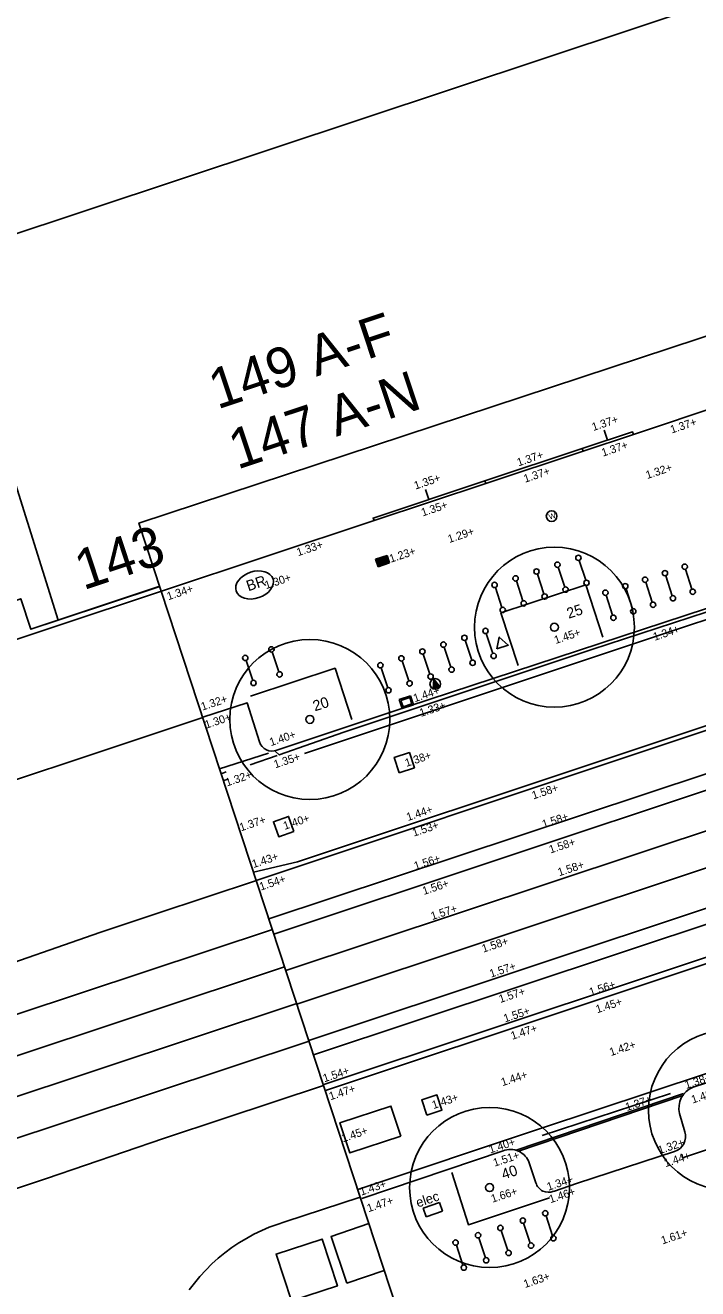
# Model space of a CAD drawing. Extents: x 122462 to 123306, y 485548 to 486417.
# Drawn here: x 122661.18 to 122686.41, y 486120.56 to 486167.94 of the extents above; entities that cross this region are included whole.
import ezdxf

# ---------------------------------------------------------------- set-up
doc = ezdxf.new("R2010")
doc.units = 0
for name, color, linetype in [('B meubilair trammast', 7, 'Continuous'), ('B RWS-band 115-225x250 mm specie', 7, 'Continuous'), ('B-WE-AL-WERKGRENS-G', 7, 'Continuous'), ('B-WE-GR-BOOM-S', 7, 'Continuous'), ('B-WE-GR-BOOM_BOOMDIAMETER', 7, 'Continuous'), ('B-WE-IE-MEUBILAIR_ELECTRAKAST', 7, 'Continuous'), ('B-WE-IE-MEUBILAIR_WEGMEUBILAIR-S', 7, 'Continuous'), ('B-WE-IE-MEUBILAIR_WEGMEUBILAIR_FIETSNIETJE-S', 7, 'Continuous'), ('B-WE-OG-BEBOUWING_PORTIEK1-G', 7, 'Continuous'), ('B-WE-OG-BEBOUWING_RAAM-G', 7, 'Continuous'), ('B-WE-OG-HOOGTEPUNT-S', 7, 'Continuous'), ('B-WE-OG-TOPOGRAFIE_RAILS-G', 7, 'Continuous'), ('B-WE-OG-TOPOKAART-G', 7, 'Continuous'), ('B-WE-RI-HWA_KOLK-S', 7, 'Continuous'), ('B-WE-RI-HWA_RIOOLPUT-S', 7, 'Continuous'), ('B-WE-VH-KANTOPSLUITING_OPSLUITBAND_100X200-G', 7, 'Continuous'), ('B-WE-VH-KANTOPSLUITING_TROTTOIRBAND_180 200-G', 7, 'Continuous'), ('B-WE-VH-KANTVERHARDING_EIND_VERHARDING-G', 7, 'Continuous'), ('B-WE-VH-MATERIAALGRENS_ASFALT-G', 7, 'Continuous'), ('B-WE-VW-MARKERING_LANGS_STREEP_11_010-G', 7, 'Continuous'), ('B-WE-VW-MARKERING_LANGS_STREEP_DOORGETROKKEN_010-G', 7, 'Continuous'), ('B-WE-VW-MARKERING_OVERIG-G', 7, 'Continuous'), ('Level 1', 7, 'Continuous'), ('Level 10', 7, 'Continuous'), ('Level 17', 7, 'Continuous'), ('Level 37', 7, 'Continuous'), ('Level 4', 7, 'Continuous'), ('Level 42', 7, 'Continuous'), ('Level 5', 7, 'Continuous'), ('Level 58', 7, 'Continuous')]:
    doc.layers.add(name, color=color, linetype=linetype)

msp = doc.modelspace()

# ---------------------------------------------------------------- linework, layer by layer
at = {"layer": 'B meubilair trammast'}
msp.add_lwpolyline([(122678.868, 486144.556), (122679.296, 486144.696), (122678.961, 486144.996)], close=True, dxfattribs=at)
at = {"layer": 'B RWS-band 115-225x250 mm specie'}
for points in [[(122669.847, 486135.87), (122698.323, 486145.37), (122705.772, 486147.833)], [(122708.301, 486140.155), (122702.829, 486138.34), (122672.345, 486128.207)]]:
    msp.add_lwpolyline(points, dxfattribs=at)
at = {"layer": 'B-WE-AL-WERKGRENS-G'}
msp.add_lwpolyline([(122857.632, 486078.279), (122830.484, 486160.606), (122900.937, 486183.81), (122887.855, 486222.555), (122665.445, 486149.273), (122678.196, 486110.449), (122807.072, 486152.895), (122835.324, 486068.154)], dxfattribs=at)
at = {"layer": 'B-WE-GR-BOOM-S'}
for centre, radius in [((122681.029, 486145.368), 3), ((122681.029, 486145.368), 0.15), ((122671.856, 486141.911), 3), ((122671.856, 486141.911), 0.15), ((122687.555, 486127.259), 3), ((122678.598, 486124.358), 3), ((122678.598, 486124.358), 0.15)]:
    msp.add_circle(centre, radius, dxfattribs=at)
for centre, start, end in [((122681.029, 486145.368), 0, 180), ((122681.029, 486145.368), 180, 0), ((122671.856, 486141.911), 0, 180), ((122671.856, 486141.911), 180, 0), ((122678.598, 486124.358), 0, 180), ((122678.598, 486124.358), 180, 0)]:
    msp.add_arc(centre, 0.15, start, end, dxfattribs=at)
at = {"layer": 'B-WE-IE-MEUBILAIR_ELECTRAKAST'}
for p, q in [((122676.103, 486123.588), (122676.718, 486123.797)), ((122676.215, 486123.257), (122676.103, 486123.588)), ((122676.83, 486123.466), (122676.215, 486123.257)), ((122676.718, 486123.797), (122676.83, 486123.466))]:
    msp.add_line(p, q, dxfattribs=at)
at = {"layer": 'B-WE-IE-MEUBILAIR_WEGMEUBILAIR-S'}
msp.add_lwpolyline([(122676.722, 486143.149), (122676.483, 486143.07), (122676.502, 486143.417), (122676.7, 486143.182), (122676.524, 486143.124), (122676.528, 486143.336), (122676.632, 486143.202), (122676.567, 486143.18), (122676.566, 486143.222), (122676.551, 486143.27)], dxfattribs=at)
for centre in [(122680.924, 486149.535), (122676.56, 486143.241)]:
    msp.add_circle(centre, 0.2, dxfattribs=at)
msp.add_ellipse((122669.784, 486146.953), major_axis=(-0.692, -0.23), ratio=0.685994, dxfattribs=at)
at = {"layer": 'B-WE-IE-MEUBILAIR_WEGMEUBILAIR_FIETSNIETJE-S'}
for p, q in [((122681.419, 486146.872), (122681.175, 486147.619)), ((122682.204, 486147.128), (122681.96, 486147.876)), ((122680.633, 486146.615), (122680.389, 486147.363)), ((122685.444, 486146.551), (122685.204, 486147.3)), ((122686.188, 486146.795), (122685.948, 486147.544)), ((122679.059, 486146.113), (122678.815, 486146.861)), ((122679.848, 486146.359), (122679.604, 486147.106)), ((122683.956, 486146.062), (122683.716, 486146.812)), ((122684.7, 486146.307), (122684.46, 486147.056)), ((122683.212, 486145.818), (122682.972, 486146.567)), ((122677.931, 486144.13), (122677.686, 486144.877)), ((122678.719, 486144.387), (122678.475, 486145.135)), ((122670.69, 486143.696), (122670.444, 486144.444)), ((122676.353, 486143.614), (122676.109, 486144.362)), ((122677.142, 486143.872), (122676.898, 486144.62)), ((122669.711, 486143.375), (122669.465, 486144.122)), ((122674.776, 486143.099), (122674.532, 486143.847)), ((122675.565, 486143.357), (122675.32, 486144.104)), ((122680.121, 486122.274), (122679.876, 486123.022)), ((122680.961, 486122.55), (122680.716, 486123.297)), ((122679.28, 486121.999), (122679.035, 486122.747)), ((122677.599, 486121.449), (122677.355, 486122.196)), ((122678.44, 486121.724), (122678.195, 486122.471))]:
    msp.add_line(p, q, dxfattribs=at)
for centre in [(122681.143, 486147.714), (122681.929, 486147.971), (122685.918, 486147.639), (122679.573, 486147.201), (122680.358, 486147.458), (122684.43, 486147.151), (122685.174, 486147.395), (122678.784, 486146.956), (122681.45, 486146.777), (122682.235, 486147.033), (122682.942, 486146.663), (122683.686, 486146.907), (122686.218, 486146.7), (122679.879, 486146.264), (122680.664, 486146.52), (122684.73, 486146.211), (122685.474, 486146.455), (122679.09, 486146.018), (122683.242, 486145.723), (122683.986, 486145.967), (122678.444, 486145.23), (122676.867, 486144.715), (122677.655, 486144.972), (122669.433, 486144.217), (122670.413, 486144.539), (122676.078, 486144.457), (122678.75, 486144.292), (122674.501, 486143.942), (122675.289, 486144.199), (122677.173, 486143.777), (122677.962, 486144.035), (122669.742, 486143.28), (122670.721, 486143.601), (122675.596, 486143.262), (122676.384, 486143.519), (122674.807, 486143.004), (122680.685, 486123.392), (122679.845, 486123.117), (122678.164, 486122.566), (122679.004, 486122.842), (122680.992, 486122.455), (122677.323, 486122.291), (122680.152, 486122.179), (122678.471, 486121.629), (122679.311, 486121.904), (122677.631, 486121.354)]:
    msp.add_circle(centre, 0.1, dxfattribs=at)
at = {"layer": 'B-WE-OG-BEBOUWING_PORTIEK1-G'}
for p, q in [((122683.019, 486152.379), (122682.893, 486152.757)), ((122676.325, 486150.16), (122676.2, 486150.536))]:
    msp.add_line(p, q, dxfattribs=at)
for points in [[(122682.106, 486151.971), (122683.995, 486152.598), (122683.963, 486152.693), (122682.074, 486152.066)], [(122674.262, 486149.366), (122678.452, 486150.758), (122678.42, 486150.856), (122674.229, 486149.464)]]:
    msp.add_lwpolyline(points, close=True, dxfattribs=at)
at = {"layer": 'B-WE-OG-BEBOUWING_RAAM-G'}
msp.add_lwpolyline([(122678.452, 486150.758), (122682.106, 486151.971), (122682.074, 486152.066), (122678.421, 486150.852)], close=True, dxfattribs=at)
at = {"layer": 'B-WE-OG-TOPOGRAFIE_RAILS-G'}
for p, q in [((122670.505, 486133.859), (122714.919, 486148.627)), ((122670.96, 486132.492), (122715.373, 486147.26)), ((122671.366, 486131.239), (122712.39, 486144.878)), ((122671.82, 486129.872), (122712.845, 486143.511))]:
    msp.add_line(p, q, dxfattribs=at)
at = {"layer": 'B-WE-OG-TOPOKAART-G'}
for points in [[(122683.995, 486152.598), (122687.4, 486153.729)], [(122666.285, 486146.717), (122674.262, 486149.366)]]:
    msp.add_lwpolyline(points, dxfattribs=at)
at = {"layer": 'B-WE-RI-HWA_KOLK-S'}
for p, q in [((122674.323, 486147.921), (122674.75, 486148.063)), ((122674.418, 486147.636), (122674.323, 486147.921)), ((122674.342, 486147.911), (122674.741, 486148.044)), ((122674.427, 486147.655), (122674.342, 486147.911)), ((122674.845, 486147.778), (122674.418, 486147.636)), ((122674.826, 486147.788), (122674.427, 486147.655)), ((122674.826, 486147.788), (122674.741, 486148.044)), ((122674.845, 486147.778), (122674.75, 486148.063)), ((122675.209, 486142.656), (122675.637, 486142.796)), ((122675.318, 486142.323), (122675.209, 486142.656)), ((122675.746, 486142.463), (122675.318, 486142.323)), ((122675.565, 486142.42), (122675.489, 486142.395)), ((122675.579, 486142.409), (122675.578, 486142.414)), ((122675.603, 486142.417), (122675.602, 486142.421)), ((122675.639, 486142.444), (122675.608, 486142.434)), ((122675.637, 486142.796), (122675.746, 486142.463)), ((122675.684, 486142.459), (122675.639, 486142.444)), ((122675.698, 486142.448), (122675.697, 486142.453)), ((122675.366, 486142.339), (122675.364, 486142.344)), ((122675.447, 486142.381), (122675.37, 486142.356)), ((122675.461, 486142.37), (122675.459, 486142.375)), ((122675.484, 486142.378), (122675.483, 486142.382))]:
    msp.add_line(p, q, dxfattribs=at)
for points in [[(122674.374, 486147.877), (122674.432, 486147.702)], [(122674.392, 486147.893), (122674.38, 486147.889)], [(122674.462, 486147.712), (122674.404, 486147.887)], [(122674.421, 486147.893), (122674.479, 486147.718)], [(122674.439, 486147.909), (122674.428, 486147.905)], [(122674.445, 486147.696), (122674.456, 486147.699)], [(122674.51, 486147.728), (122674.452, 486147.903)], [(122674.469, 486147.908), (122674.527, 486147.733)], [(122674.486, 486147.925), (122674.475, 486147.921)], [(122674.492, 486147.711), (122674.503, 486147.715)], [(122674.557, 486147.744), (122674.499, 486147.918)], [(122674.516, 486147.924), (122674.574, 486147.749)], [(122674.534, 486147.94), (122674.523, 486147.937)], [(122674.539, 486147.727), (122674.551, 486147.731)], [(122674.605, 486147.759), (122674.547, 486147.934)], [(122674.564, 486147.94), (122674.622, 486147.765)], [(122674.581, 486147.956), (122674.57, 486147.952)], [(122674.587, 486147.743), (122674.598, 486147.747)], [(122674.652, 486147.775), (122674.594, 486147.95)], [(122674.611, 486147.956), (122674.669, 486147.781)], [(122674.629, 486147.972), (122674.617, 486147.968)], [(122674.634, 486147.759), (122674.646, 486147.762)], [(122674.7, 486147.791), (122674.641, 486147.966)], [(122674.659, 486147.971), (122674.717, 486147.796)], [(122674.676, 486147.988), (122674.665, 486147.984)], [(122674.682, 486147.774), (122674.693, 486147.778)], [(122674.747, 486147.807), (122674.689, 486147.981)], [(122674.706, 486147.987), (122674.764, 486147.812)], [(122674.724, 486148.004), (122674.712, 486148)], [(122674.729, 486147.79), (122674.741, 486147.794)], [(122674.794, 486147.822), (122674.736, 486147.997)], [(122674.777, 486147.806), (122674.788, 486147.81)]]:
    msp.add_lwpolyline(points, dxfattribs=at)
msp.add_lwpolyline([(122675.272, 486142.624), (122675.605, 486142.733), (122675.683, 486142.495), (122675.35, 486142.386)], close=True, dxfattribs=at)
for centre, start, end in [((122674.383, 486147.88), 108.372, 198.372), ((122674.395, 486147.884), 18.372, 108.372), ((122674.431, 486147.896), 108.372, 198.372), ((122674.441, 486147.705), 198.372, 288.372), ((122674.442, 486147.899), 18.372, 108.372), ((122674.453, 486147.709), 288.372, 18.372), ((122674.478, 486147.911), 108.372, 198.372), ((122674.489, 486147.721), 198.372, 288.372), ((122674.49, 486147.915), 18.372, 108.372), ((122674.5, 486147.725), 288.372, 18.372), ((122674.526, 486147.927), 108.372, 198.372), ((122674.536, 486147.737), 198.372, 288.372), ((122674.537, 486147.931), 18.372, 108.372), ((122674.548, 486147.74), 288.372, 18.372), ((122674.573, 486147.943), 108.372, 198.372), ((122674.584, 486147.752), 198.372, 288.372), ((122674.585, 486147.947), 18.372, 108.372), ((122674.595, 486147.756), 288.372, 18.372), ((122674.621, 486147.959), 108.372, 198.372), ((122674.631, 486147.768), 198.372, 288.372), ((122674.632, 486147.963), 18.372, 108.372), ((122674.643, 486147.772), 288.372, 18.372), ((122674.668, 486147.974), 108.372, 198.372), ((122674.679, 486147.784), 198.372, 288.372), ((122674.679, 486147.978), 18.372, 108.372), ((122674.69, 486147.788), 288.372, 18.372), ((122674.716, 486147.99), 108.372, 198.372), ((122674.726, 486147.8), 198.372, 288.372), ((122674.727, 486147.994), 18.372, 108.372), ((122674.738, 486147.803), 288.372, 18.372), ((122674.774, 486147.815), 198.372, 288.372), ((122674.785, 486147.819), 288.372, 18.372), ((122675.568, 486142.41), 18.1337, 108.1337), ((122675.611, 486142.424), 108.1337, 198.1337), ((122675.687, 486142.449), 18.1337, 108.1337), ((122675.374, 486142.347), 108.1337, 198.1337), ((122675.45, 486142.372), 18.1337, 108.1337), ((122675.492, 486142.386), 108.1337, 198.1337)]:
    msp.add_arc(centre, 0.01, start, end, dxfattribs=at)
at = {"layer": 'B-WE-RI-HWA_RIOOLPUT-S'}
for points in [[(122675.208, 486139.914), (122675.778, 486140.1), (122675.592, 486140.67), (122675.022, 486140.484)], [(122671.255, 486137.707), (122671.057, 486138.273), (122670.491, 486138.075), (122670.689, 486137.509)], [(122676.24, 486127.072), (122676.809, 486127.261), (122676.62, 486127.83), (122676.051, 486127.641)]]:
    msp.add_lwpolyline(points, close=True, dxfattribs=at)
at = {"layer": 'B-WE-VH-KANTOPSLUITING_OPSLUITBAND_100X200-G'}
for points in [[(122679.674, 486143.931), (122679.024, 486145.91), (122682.204, 486146.954), (122682.85, 486144.998)], [(122669.625, 486142.786), (122672.803, 486143.832), (122673.43, 486141.914)]]:
    msp.add_lwpolyline(points, dxfattribs=at)
at = {"layer": 'B-WE-VH-KANTOPSLUITING_TROTTOIRBAND_180 200-G'}
for points in [[(122689.134, 486146.852), (122675.531, 486142.397), (122670.617, 486140.763)], [(122669.969, 486141.067), (122669.506, 486142.533), (122667.837, 486141.99)], [(122686.229, 486128.118), (122688.811, 486128.965)], [(122685.928, 486126.45), (122685.725, 486127.134)], [(122673.81, 486123.945), (122679.103, 486125.736)], [(122680.999, 486124.215), (122681.896, 486124.516), (122685.539, 486125.709)], [(122680.084, 486125.284), (122680.335, 486124.537)]]:
    msp.add_lwpolyline(points, dxfattribs=at)
for centre, radius, start, end in [((122670.43, 486141.208), 0.482, 196.9682, 292.7659), ((122686.532, 486127.342), 0.833, 111.3234, 194.434), ((122685.353, 486126.279), 0.6, 288.1341, 16.5237), ((122679.374, 486125.033), 0.753, 19.4554, 111.0684), ((122680.81, 486124.671), 0.493, 195.7392, 292.5197)]:
    msp.add_arc(centre, radius, start, end, dxfattribs=at)
at = {"layer": 'B-WE-VH-KANTVERHARDING_EIND_VERHARDING-G'}
for points in [[(122685.809, 486125.603), (122685.84, 486125.468), (122690.695, 486127.088), (122690.628, 486127.234)], [(122677.176, 486124.92), (122677.804, 486122.964), (122680.842, 486123.967)]]:
    msp.add_lwpolyline(points, dxfattribs=at)
at = {"layer": 'B-WE-VH-MATERIAALGRENS_ASFALT-G'}
for points in [[(122689.178, 486146.73), (122682.431, 486144.534), (122673.133, 486141.431), (122670.707, 486140.578), (122670.551, 486140.725)], [(122670.318, 486134.438), (122689.137, 486140.666), (122697.659, 486143.491), (122706.259, 486146.355)], [(122707.935, 486141.266), (122704.407, 486140.099), (122695.913, 486137.294), (122687.388, 486134.451), (122671.994, 486129.333)], [(122668.472, 486140.058), (122670.299, 486140.643)], [(122685.868, 486127.886), (122679.595, 486125.753)]]:
    msp.add_lwpolyline(points, dxfattribs=at)
at = {"layer": 'B-WE-VW-MARKERING_LANGS_STREEP_11_010-G'}
for points in [[(122701.228, 486150.481), (122671.658, 486140.638)], [(122709.603, 486136.203), (122680.508, 486126.571), (122673.652, 486124.285)], [(122685.382, 486127.887), (122680.57, 486126.307)]]:
    msp.add_lwpolyline(points, dxfattribs=at)
at = {"layer": 'B-WE-VW-MARKERING_LANGS_STREEP_DOORGETROKKEN_010-G'}
msp.add_line((122685.846, 486127.815), (122679.651, 486125.709), dxfattribs=at)
for points in [[(122669.745, 486136.183), (122671.391, 486136.575), (122705.718, 486147.995)], [(122670.624, 486140.557), (122669.619, 486140.212)], [(122668.533, 486139.872), (122668.716, 486139.94)], [(122668.803, 486139.676), (122668.617, 486139.615)], [(122708.366, 486139.96), (122701.962, 486137.822), (122672.4, 486127.989)]]:
    msp.add_lwpolyline(points, dxfattribs=at)
at = {"layer": 'B-WE-VW-MARKERING_OVERIG-G'}
msp.add_lwpolyline([(122675.265, 486126.283), (122673.357, 486125.657), (122672.986, 486126.787), (122674.894, 486127.414)], close=True, dxfattribs=at)
at = {"layer": 'Level 1'}
for points in [[(122666.224, 486146.901), (122662.417, 486145.637)], [(122662.417, 486145.637), (122661.386, 486145.295), (122661.008, 486146.434), (122653.684, 486144.002), (122654.062, 486142.863), (122641.82, 486138.797), (122641.442, 486139.936), (122635.639, 486138.009), (122636.017, 486136.87), (122610.508, 486128.398), (122609.476, 486131.683)]]:
    msp.add_lwpolyline(points, dxfattribs=at)
at = {"layer": 'Level 10'}
for points in [[(122593.88, 486122.67), (122581.87, 486160.871), (122582.347, 486161.021), (122593.17, 486126.596), (122609.476, 486131.683), (122610.508, 486128.398), (122636.017, 486136.87), (122635.639, 486138.009), (122641.442, 486139.936), (122641.82, 486138.797), (122654.062, 486142.863), (122653.684, 486144.002), (122661.008, 486146.434), (122661.386, 486145.295), (122666.224, 486146.902)], [(122666.285, 486146.717), (122593.88, 486122.67)]]:
    msp.add_lwpolyline(points, dxfattribs=at)
at = {"layer": 'Level 17'}
for points in [[(122660.122, 486139.42), (122664.051, 486140.727), (122667.839, 486141.987)], [(122594.012, 486108.696), (122593.441, 486110.391), (122618.251, 486118.741), (122659.381, 486132.321), (122663.981, 486133.921), (122666.083, 486134.619), (122669.848, 486135.869)], [(122595.43, 486104.48), (122596.004, 486102.775), (122661.971, 486124.691), (122666.371, 486126.201), (122668.634, 486126.951), (122672.37, 486128.188)], [(122673.746, 486124), (122670.919, 486123.07), (122670.624, 486122.975), (122670.333, 486122.867), (122670.048, 486122.746), (122669.757, 486122.606), (122669.473, 486122.452), (122669.197, 486122.285), (122668.929, 486122.105), (122668.67, 486121.912), (122668.42, 486121.707), (122668.181, 486121.491), (122667.952, 486121.263), (122667.734, 486121.025), (122667.528, 486120.776), (122667.334, 486120.518)]]:
    msp.add_lwpolyline(points, dxfattribs=at)
at = {"layer": 'Level 37'}
for p, q in [((122670.91, 486132.634), (122575.077, 486100.86)), ((122671.362, 486131.258), (122572.236, 486098.337)), ((122671.824, 486129.851), (122564.447, 486094.19))]:
    msp.add_line(p, q, dxfattribs=at)
msp.add_lwpolyline([(122577, 486103.056), (122670.449, 486134.039)], dxfattribs=at)
at = {"layer": 'Level 4'}
msp.add_line((122658.143, 486159.234), (122662.417, 486145.637), dxfattribs=at)
at = {"layer": 'Level 42'}
for points in [[(122673.244, 486120.776), (122672.654, 486122.527), (122674.073, 486123.005)], [(122671.162, 486120.108), (122670.589, 486121.861), (122672.315, 486122.424), (122672.887, 486120.671), (122671.162, 486120.108)], [(122674.649, 486121.249), (122673.244, 486120.776)]]:
    msp.add_lwpolyline(points, dxfattribs=at)
at = {"layer": 'Level 5'}
msp.add_line((122658.143, 486159.234), (122711.887, 486177.083), dxfattribs=at)

# ---------------------------------------------------------------- texts
at = {"layer": 'B-WE-GR-BOOM_BOOMDIAMETER'}
for s, rotation, p in [('25', 18.1724, (122681.567, 486145.683)), ('20', 18.1724, (122672.045, 486142.21)), ('40', 18.3203, (122679.12, 486124.652))]:
    msp.add_text(s, height=0.4, rotation=rotation, dxfattribs=at).set_placement(p)
at = {"layer": 'B-WE-IE-MEUBILAIR_ELECTRAKAST'}
msp.add_text('elec', height=0.36, rotation=18.6998, dxfattribs=at).set_placement((122675.907, 486123.605))
at = {"layer": 'B-WE-IE-MEUBILAIR_WEGMEUBILAIR-S'}
for s, height, p in [('W', 0.2, (122680.856, 486149.401)), ('BR', 0.4, (122669.549, 486146.714))]:
    msp.add_text(s, height=height, rotation=18.372, dxfattribs=at).set_placement(p)
at = {"layer": 'B-WE-OG-HOOGTEPUNT-S'}
for s, rotation, p in [('1.37+', 18.372, (122682.489, 486152.725)), ('1.37+', 18.372, (122685.433, 486152.63)), ('1.37+', 18.372, (122679.682, 486151.397)), ('1.37+', 18.372, (122682.854, 486151.764)), ('1.32+', 18.372, (122684.511, 486150.922)), ('1.35+', 18.372, (122675.821, 486150.529)), ('1.37+', 18.372, (122679.932, 486150.786)), ('1.35+', 18.372, (122676.089, 486149.52)), ('1.29+', 18.372, (122677.086, 486148.525)), ('1.33+', 18.372, (122671.416, 486148.029)), ('1.23+', 18.372, (122674.893, 486147.787)), ('1.30+', 18.372, (122670.217, 486146.795)), ('1.34+', 18.372, (122666.546, 486146.377)), ('1.45+', 18.5166, (122681.078, 486144.736)), ('1.34+', 18.4111, (122684.79, 486144.858)), ('1.44+', 18.4494, (122675.793, 486142.556)), ('1.32+', 18.4553, (122667.828, 486142.24)), ('1.33+', 18.4553, (122676.023, 486142.003)), ('1.30+', 18.4553, (122667.971, 486141.561)), ('1.40+', 18.4553, (122670.397, 486140.908)), ('1.35+', 18.4553, (122670.559, 486140.074)), ('1.38+', 18.4553, (122675.479, 486140.129)), ('1.32+', 18.4553, (122668.749, 486139.397)), ('1.58+', 18.3037, (122680.239, 486138.91)), ('1.44+', 18.4494, (122675.534, 486138.098)), ('1.37+', 18.4553, (122669.271, 486137.713)), ('1.40+', 18.4553, (122670.914, 486137.77)), ('1.58+', 18.3037, (122680.621, 486137.833)), ('1.53+', 18.3037, (122675.756, 486137.513)), ('1.58+', 18.3037, (122680.882, 486136.88)), ('1.43+', 18.4553, (122669.741, 486136.335)), ('1.56+', 18.3037, (122675.817, 486136.265)), ('1.58+', 18.3037, (122681.209, 486136.027)), ('1.54+', 18.4553, (122670.019, 486135.49)), ('1.56+', 18.3037, (122676.134, 486135.328)), ('1.57+', 18.3037, (122676.446, 486134.384)), ('1.58+', 18.3037, (122678.365, 486133.163)), ('1.57+', 18.3037, (122678.651, 486132.226)), ('1.56+', 18.1815, (122682.391, 486131.537)), ('1.57+', 18.3037, (122678.999, 486131.277)), ('1.55+', 18.3037, (122679.177, 486130.547)), ('1.45+', 18.1815, (122682.636, 486130.891)), ('1.47+', 18.3037, (122679.449, 486129.896)), ('1.42+', 18.1815, (122683.148, 486129.285)), ('1.54+', 18.387, (122672.402, 486128.303)), ('1.44+', 18.1815, (122679.083, 486128.156)), ('1.38+', 18.1815, (122685.975, 486128.053)), ('1.47+', 18.387, (122672.632, 486127.629)), ('1.43+', 18.6944, (122676.494, 486127.299)), ('1.37+', 18.1815, (122683.747, 486127.223)), ('1.48+', 18.1815, (122686.22, 486127.505)), ('1.45+', 18.6944, (122673.096, 486126.051)), ('1.40+', 18.1815, (122678.623, 486125.632)), ('1.32+', 18.1815, (122684.972, 486125.609)), ('1.51+', 18.1815, (122678.786, 486125.137)), ('1.44+', 18.1815, (122685.198, 486125.119)), ('1.43+', 18.6944, (122673.787, 486124.052)), ('1.34+', 18.1815, (122680.801, 486124.236)), ('1.47+', 18.6944, (122674.056, 486123.43)), ('1.66+', 18.1815, (122678.706, 486123.787)), ('1.46+', 18.1815, (122680.882, 486123.77)), ('1.61+', 18.6944, (122685.089, 486122.223)), ('1.63+', 18.6944, (122679.93, 486120.588))]:
    msp.add_text(s, height=0.3, rotation=rotation, dxfattribs=at).set_placement(p)
at = {"layer": 'Level 58'}
for s, rotation, p in [('149 A-F', 18.3704, (122668.386, 486153.531)), ('147 A-N', 18.3704, (122669.135, 486151.274)), ('143', 18.3743, (122663.356, 486146.751))]:
    msp.add_text(s, height=1.5, rotation=rotation, dxfattribs=at).set_placement(p)

doc.saveas('drawing.dxf')
